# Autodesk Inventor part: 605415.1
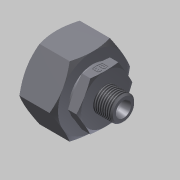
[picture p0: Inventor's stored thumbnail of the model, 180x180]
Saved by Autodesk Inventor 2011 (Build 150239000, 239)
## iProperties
Created: 2014-03
Part Number: 605415.1
Material: Сталь
Document SubType Name: Modeling
Designer: dorohin
Mass: 369.402 g
Surface Area: 127.284 cm^2
Volume: 47.0576 cm^3
Density: 7.85 g/cm^3
Стандарт преобразования: STEP AP203
Имя файла: C:/Users/dorohin/Documents/EO Tube end reducer RED25_08SOMDCF.stp
Постпроцессор: Build: 309, Release: 2011 SP2 - Date: Thu 04/28/2011
Отправленные единицы: миллиметр
Неопределенность: 1.0000000000000002e-06
Author: dorohin
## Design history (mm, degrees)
feature "БазТело1"
feature "Резьба1" dims "d0" = 10, "d1" = 0
feature "Резьба2" dims "d2" = 10, "d3" = 0
node "1"
